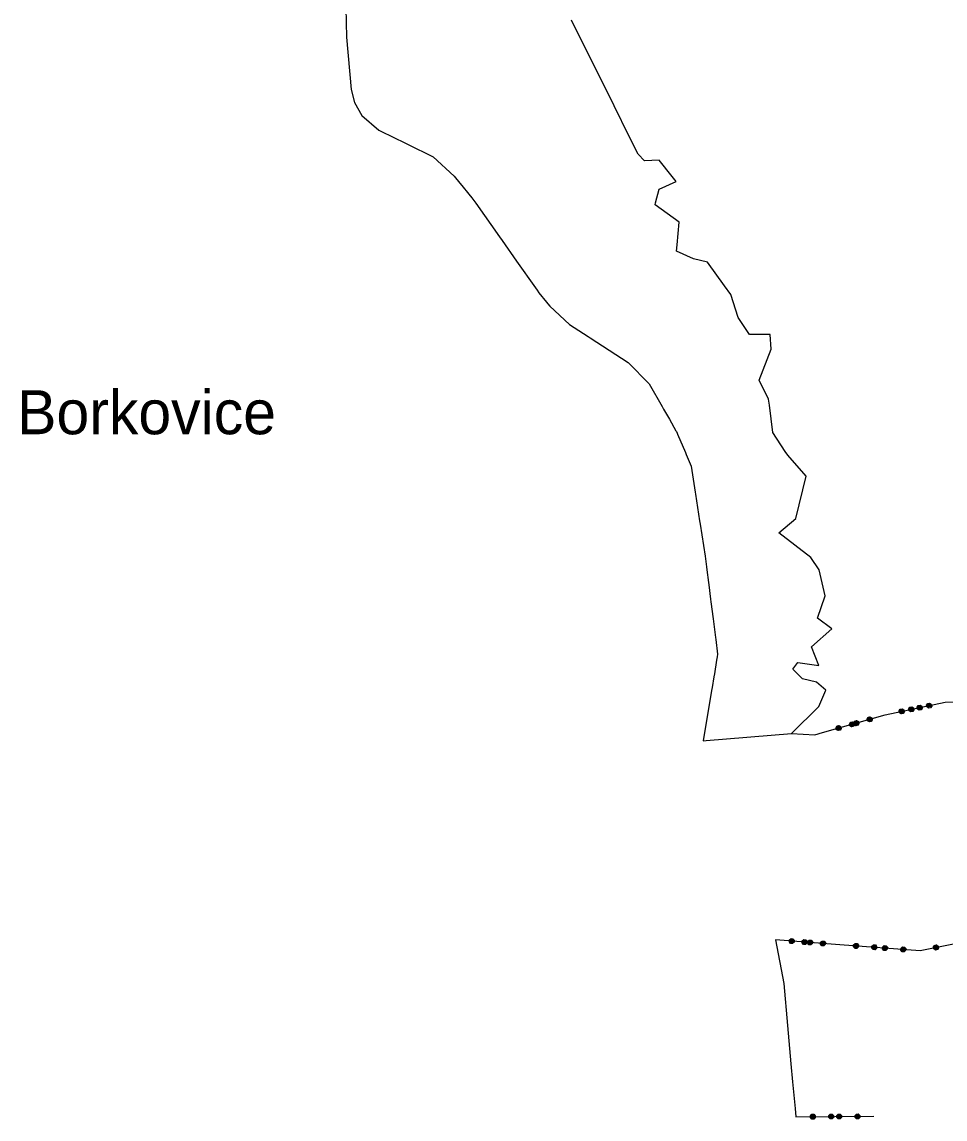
# Model space of a CAD drawing. Extents: x -738939 to -735528, y -1140462 to -1136895.
# Drawn here: x -738939 to -738311, y -1140462 to -1139715 of the extents above; entities that cross this region are included whole.
import ezdxf

# ---------------------------------------------------------------- set-up
doc = ezdxf.new("R2010")
doc.units = 0
for name, color, linetype in [('HRA_KU', 7, 'Continuous'), ('KU_OST', 7, 'Continuous'), ('OVNE_PRE', 7, 'Continuous')]:
    doc.layers.add(name, color=color, linetype=linetype)

msp = doc.modelspace()

# ---------------------------------------------------------------- linework, layer by layer
at = {"layer": 'HRA_KU'}
for points in [[(-738414.99, -1140199.58), (-738399.12, -1140200.49), (-738393.99, -1140199.05), (-738351.21, -1140187.04), (-738310.54, -1140178.29), (-738300.41, -1140178)], [(-738327.45, -1140180.29), (-738326.32, -1140181.02), (-738326.04, -1140182.34), (-738326.76, -1140183.47), (-738328.08, -1140183.75), (-738329.21, -1140183.02), (-738329.5, -1140181.7), (-738328.77, -1140180.57), (-738327.45, -1140180.29), (-738327.55, -1140180.52), (-738328.73, -1140180.77), (-738329.03, -1140181.25), (-738327.08, -1140180.82), (-738326.6, -1140181.13), (-738329.34, -1140181.72), (-738329.26, -1140182.11), (-738326.52, -1140181.52), (-738326.43, -1140181.91), (-738329.17, -1140182.5), (-738329.09, -1140182.89), (-738326.35, -1140182.3), (-738326.66, -1140182.78), (-738328.61, -1140183.2), (-738328.14, -1140183.51), (-738326.96, -1140183.25)], [(-738321, -1140178.9), (-738319.87, -1140179.63), (-738319.58, -1140180.95), (-738320.31, -1140182.08), (-738321.63, -1140182.36), (-738322.76, -1140181.63), (-738323.04, -1140180.31), (-738322.32, -1140179.19), (-738321, -1140178.9), (-738321.1, -1140179.13), (-738322.27, -1140179.38), (-738322.58, -1140179.86), (-738320.62, -1140179.44), (-738320.15, -1140179.74), (-738322.89, -1140180.33), (-738322.8, -1140180.72), (-738320.07, -1140180.13), (-738319.98, -1140180.53), (-738322.72, -1140181.11), (-738322.63, -1140181.51), (-738319.9, -1140180.92), (-738320.2, -1140181.39), (-738322.16, -1140181.81), (-738321.68, -1140182.12), (-738320.51, -1140181.87)], [(-738339.67, -1140182.92), (-738338.54, -1140183.65), (-738338.26, -1140184.97), (-738338.98, -1140186.1), (-738340.3, -1140186.38), (-738341.43, -1140185.65), (-738341.72, -1140184.33), (-738340.99, -1140183.2), (-738339.67, -1140182.92), (-738339.68, -1140183.13), (-738340.85, -1140183.38), (-738341.16, -1140183.85), (-738339.2, -1140183.43), (-738338.72, -1140183.74), (-738341.46, -1140184.33), (-738341.38, -1140184.72), (-738338.64, -1140184.13), (-738338.56, -1140184.52), (-738341.29, -1140185.11), (-738341.21, -1140185.5), (-738338.47, -1140184.91), (-738338.78, -1140185.39), (-738340.73, -1140185.81), (-738340.26, -1140186.12), (-738339.09, -1140185.86)], [(-738333.22, -1140181.53), (-738332.09, -1140182.26), (-738331.8, -1140183.58), (-738332.53, -1140184.71), (-738333.85, -1140184.99), (-738334.98, -1140184.26), (-738335.26, -1140182.95), (-738334.54, -1140181.82), (-738333.22, -1140181.53), (-738333.22, -1140181.74), (-738334.4, -1140181.99), (-738334.7, -1140182.47), (-738332.75, -1140182.05), (-738332.27, -1140182.35), (-738335.01, -1140182.94), (-738334.92, -1140183.33), (-738332.19, -1140182.74), (-738332.1, -1140183.13), (-738334.84, -1140183.72), (-738334.76, -1140184.11), (-738332.02, -1140183.53), (-738332.33, -1140184), (-738334.28, -1140184.42), (-738333.81, -1140184.73), (-738332.63, -1140184.48)], [(-738382.72, -1140194.23), (-738381.55, -1140194.88), (-738381.19, -1140196.18), (-738381.85, -1140197.36), (-738383.14, -1140197.72), (-738384.32, -1140197.06), (-738384.68, -1140195.76), (-738384.02, -1140194.59), (-738382.72, -1140194.23), (-738382.72, -1140194.43), (-738383.87, -1140194.76), (-738384.15, -1140195.25), (-738382.23, -1140194.71), (-738381.73, -1140194.99), (-738384.43, -1140195.74), (-738384.32, -1140196.13), (-738381.62, -1140195.37), (-738381.52, -1140195.76), (-738384.21, -1140196.51), (-738384.1, -1140196.9), (-738381.41, -1140196.14), (-738381.68, -1140196.64), (-738383.61, -1140197.18), (-738383.12, -1140197.45), (-738381.96, -1140197.13)], [(-738373.64, -1140191.68), (-738372.47, -1140192.33), (-738372.11, -1140193.63), (-738372.76, -1140194.81), (-738374.06, -1140195.17), (-738375.23, -1140194.51), (-738375.6, -1140193.21), (-738374.94, -1140192.04), (-738373.64, -1140191.68), (-738373.64, -1140191.88), (-738374.79, -1140192.21), (-738375.07, -1140192.7), (-738373.14, -1140192.16), (-738372.65, -1140192.44), (-738375.34, -1140193.19), (-738375.24, -1140193.58), (-738372.54, -1140192.82), (-738372.43, -1140193.21), (-738375.13, -1140193.96), (-738375.02, -1140194.35), (-738372.32, -1140193.59), (-738372.6, -1140194.09), (-738374.53, -1140194.63), (-738374.03, -1140194.9), (-738372.88, -1140194.58)], [(-738370.69, -1140190.84), (-738369.52, -1140191.5), (-738369.15, -1140192.8), (-738369.81, -1140193.97), (-738371.11, -1140194.34), (-738372.28, -1140193.68), (-738372.65, -1140192.38), (-738371.99, -1140191.21), (-738370.69, -1140190.84), (-738370.78, -1140191.08), (-738371.94, -1140191.4), (-738372.21, -1140191.9), (-738370.29, -1140191.35), (-738369.79, -1140191.63), (-738372.49, -1140192.39), (-738372.38, -1140192.77), (-738369.69, -1140192.02), (-738369.58, -1140192.4), (-738372.27, -1140193.16), (-738372.17, -1140193.54), (-738369.47, -1140192.79), (-738369.75, -1140193.28), (-738371.67, -1140193.82), (-738371.18, -1140194.1), (-738370.02, -1140193.77)], [(-738361.61, -1140188.3), (-738360.44, -1140188.95), (-738360.07, -1140190.25), (-738360.73, -1140191.42), (-738362.03, -1140191.79), (-738363.2, -1140191.13), (-738363.57, -1140189.83), (-738362.91, -1140188.66), (-738361.61, -1140188.3), (-738361.7, -1140188.53), (-738362.85, -1140188.85), (-738363.13, -1140189.35), (-738361.21, -1140188.81), (-738360.71, -1140189.08), (-738363.41, -1140189.84), (-738363.3, -1140190.22), (-738360.6, -1140189.47), (-738360.5, -1140189.85), (-738363.19, -1140190.61), (-738363.08, -1140190.99), (-738360.39, -1140190.24), (-738360.66, -1140190.73), (-738362.59, -1140191.27), (-738362.1, -1140191.55), (-738360.94, -1140191.22)], [(-738241.47, -1140330.32), (-738327.46, -1140347.5), (-738382.19, -1140343.52), (-738425.77, -1140340.11), (-738420.11, -1140369.81), (-738417.67, -1140398.44), (-738415.46, -1140424.43), (-738414.4, -1140436.82), (-738412.51, -1140455.01), (-738411.93, -1140460.53), (-738359.03, -1140460.24)], [(-738415.58, -1140342.52), (-738416.45, -1140341.5), (-738416.34, -1140340.15), (-738415.32, -1140339.28), (-738413.98, -1140339.38), (-738413.1, -1140340.4), (-738413.21, -1140341.75), (-738414.23, -1140342.62), (-738415.58, -1140342.52), (-738415.41, -1140342.33), (-738414.21, -1140342.42), (-738413.78, -1140342.05), (-738415.78, -1140341.9), (-738416.15, -1140341.47), (-738413.35, -1140341.69), (-738413.32, -1140341.29), (-738416.12, -1140341.07), (-738416.08, -1140340.67), (-738413.29, -1140340.89), (-738413.26, -1140340.49), (-738416.05, -1140340.27), (-738415.62, -1140339.9), (-738413.63, -1140340.06), (-738414, -1140339.63), (-738415.19, -1140339.54)], [(-738406.89, -1140343.2), (-738407.76, -1140342.18), (-738407.66, -1140340.83), (-738406.64, -1140339.96), (-738405.29, -1140340.06), (-738404.42, -1140341.08), (-738404.52, -1140342.43), (-738405.54, -1140343.3), (-738406.89, -1140343.2), (-738406.72, -1140343.01), (-738405.53, -1140343.1), (-738405.1, -1140342.73), (-738407.09, -1140342.58), (-738407.46, -1140342.15), (-738404.67, -1140342.37), (-738404.64, -1140341.97), (-738407.43, -1140341.75), (-738407.4, -1140341.35), (-738404.61, -1140341.57), (-738404.58, -1140341.17), (-738407.37, -1140340.95), (-738406.94, -1140340.58), (-738404.94, -1140340.74), (-738405.31, -1140340.31), (-738406.51, -1140340.22)], [(-738403.11, -1140343.49), (-738403.99, -1140342.46), (-738403.88, -1140341.12), (-738402.86, -1140340.24), (-738401.52, -1140340.35), (-738400.64, -1140341.37), (-738400.75, -1140342.72), (-738401.77, -1140343.59), (-738403.11, -1140343.49), (-738403.05, -1140343.29), (-738401.85, -1140343.38), (-738401.42, -1140343.01), (-738403.42, -1140342.86), (-738403.78, -1140342.43), (-738400.99, -1140342.65), (-738400.96, -1140342.25), (-738403.75, -1140342.03), (-738403.72, -1140341.63), (-738400.93, -1140341.85), (-738400.9, -1140341.45), (-738403.69, -1140341.23), (-738403.26, -1140340.87), (-738401.27, -1140341.02), (-738401.63, -1140340.59), (-738402.83, -1140340.5)], [(-738394.43, -1140344.16), (-738395.3, -1140343.14), (-738395.2, -1140341.8), (-738394.17, -1140340.92), (-738392.83, -1140341.03), (-738391.96, -1140342.05), (-738392.06, -1140343.4), (-738393.08, -1140344.27), (-738394.43, -1140344.16), (-738394.36, -1140343.97), (-738393.17, -1140344.06), (-738392.74, -1140343.69), (-738394.73, -1140343.54), (-738395.1, -1140343.11), (-738392.31, -1140343.33), (-738392.27, -1140342.93), (-738395.07, -1140342.71), (-738395.04, -1140342.31), (-738392.24, -1140342.53), (-738392.21, -1140342.13), (-738395, -1140341.91), (-738394.57, -1140341.55), (-738392.58, -1140341.7), (-738392.95, -1140341.27), (-738394.14, -1140341.18)], [(-738371.98, -1140345.87), (-738372.86, -1140344.85), (-738372.76, -1140343.5), (-738371.75, -1140342.63), (-738370.4, -1140342.72), (-738369.52, -1140343.74), (-738369.62, -1140345.09), (-738370.64, -1140345.96), (-738371.98, -1140345.87), (-738371.82, -1140345.68), (-738370.62, -1140345.76), (-738370.19, -1140345.39), (-738372.19, -1140345.25), (-738372.56, -1140344.82), (-738369.77, -1140345.03), (-738369.74, -1140344.63), (-738372.53, -1140344.42), (-738372.5, -1140344.02), (-738369.71, -1140344.23), (-738369.68, -1140343.83), (-738372.47, -1140343.63), (-738372.04, -1140343.26), (-738370.05, -1140343.4), (-738370.42, -1140342.97), (-738371.62, -1140342.89)], [(-738359.52, -1140346.77), (-738360.39, -1140345.76), (-738360.3, -1140344.41), (-738359.28, -1140343.53), (-738357.93, -1140343.63), (-738357.06, -1140344.65), (-738357.15, -1140345.99), (-738358.17, -1140346.87), (-738359.52, -1140346.77), (-738359.45, -1140346.58), (-738358.26, -1140346.66), (-738357.83, -1140346.29), (-738359.82, -1140346.15), (-738360.19, -1140345.72), (-738357.4, -1140345.92), (-738357.37, -1140345.53), (-738360.16, -1140345.32), (-738360.13, -1140344.92), (-738357.34, -1140345.13), (-738357.31, -1140344.73), (-738360.1, -1140344.52), (-738359.68, -1140344.15), (-738357.68, -1140344.3), (-738358.05, -1140343.87), (-738359.25, -1140343.78)], [(-738352.16, -1140347.31), (-738353.04, -1140346.29), (-738352.94, -1140344.95), (-738351.93, -1140344.07), (-738350.58, -1140344.16), (-738349.7, -1140345.18), (-738349.8, -1140346.53), (-738350.81, -1140347.41), (-738352.16, -1140347.31), (-738352, -1140347.12), (-738350.8, -1140347.21), (-738350.37, -1140346.84), (-738352.37, -1140346.69), (-738352.74, -1140346.26), (-738349.94, -1140346.47), (-738349.92, -1140346.07), (-738352.71, -1140345.86), (-738352.68, -1140345.47), (-738349.89, -1140345.67), (-738349.86, -1140345.27), (-738352.65, -1140345.07), (-738352.22, -1140344.7), (-738350.23, -1140344.84), (-738350.6, -1140344.41), (-738351.79, -1140344.33)], [(-738339.69, -1140348.21), (-738340.57, -1140347.2), (-738340.47, -1140345.85), (-738339.46, -1140344.97), (-738338.11, -1140345.07), (-738337.23, -1140346.09), (-738337.33, -1140347.43), (-738338.35, -1140348.31), (-738339.69, -1140348.21), (-738339.63, -1140348.02), (-738338.43, -1140348.11), (-738338, -1140347.74), (-738340, -1140347.59), (-738340.37, -1140347.16), (-738337.58, -1140347.37), (-738337.55, -1140346.97), (-738340.34, -1140346.76), (-738340.31, -1140346.36), (-738337.52, -1140346.57), (-738337.49, -1140346.17), (-738340.28, -1140345.97), (-738339.85, -1140345.6), (-738337.86, -1140345.74), (-738338.23, -1140345.31), (-738339.43, -1140345.23)], [(-738317, -1140347.04), (-738318.11, -1140346.3), (-738318.38, -1140344.97), (-738317.63, -1140343.86), (-738316.31, -1140343.59), (-738315.19, -1140344.34), (-738314.93, -1140345.66), (-738315.67, -1140346.78), (-738317, -1140347.04), (-738316.89, -1140346.82), (-738315.71, -1140346.58), (-738315.4, -1140346.11), (-738317.36, -1140346.5), (-738317.83, -1140346.19), (-738315.08, -1140345.64), (-738315.16, -1140345.25), (-738317.91, -1140345.8), (-738317.99, -1140345.41), (-738315.24, -1140344.86), (-738315.32, -1140344.46), (-738318.07, -1140345.01), (-738317.75, -1140344.54), (-738315.79, -1140344.15), (-738316.26, -1140343.84), (-738317.44, -1140344.07)], [(-738399.79, -1140458.86), (-738398.83, -1140459.81), (-738398.83, -1140461.16), (-738399.77, -1140462.11), (-738401.12, -1140462.12), (-738402.08, -1140461.17), (-738402.08, -1140459.82), (-738401.14, -1140458.87), (-738399.79, -1140458.86), (-738399.84, -1140459.06), (-738401.04, -1140459.07), (-738401.44, -1140459.47), (-738399.44, -1140459.46), (-738399.03, -1140459.86), (-738401.83, -1140459.87), (-738401.83, -1140460.27), (-738399.03, -1140460.26), (-738399.03, -1140460.66), (-738401.83, -1140460.67), (-738401.83, -1140461.07), (-738399.03, -1140461.06), (-738399.43, -1140461.46), (-738401.43, -1140461.47), (-738401.02, -1140461.87), (-738399.82, -1140461.86)], [(-738387.29, -1140458.8), (-738386.33, -1140459.74), (-738386.33, -1140461.09), (-738387.27, -1140462.05), (-738388.62, -1140462.06), (-738389.58, -1140461.11), (-738389.58, -1140459.76), (-738388.64, -1140458.81), (-738387.29, -1140458.8), (-738387.44, -1140459), (-738388.64, -1140459.01), (-738389.04, -1140459.41), (-738387.04, -1140459.4), (-738386.63, -1140459.8), (-738389.43, -1140459.81), (-738389.43, -1140460.21), (-738386.63, -1140460.2), (-738386.63, -1140460.6), (-738389.43, -1140460.61), (-738389.43, -1140461.01), (-738386.63, -1140461), (-738387.03, -1140461.4), (-738389.03, -1140461.41), (-738388.62, -1140461.81), (-738387.42, -1140461.8)], [(-738381.89, -1140458.76), (-738380.93, -1140459.71), (-738380.93, -1140461.06), (-738381.87, -1140462.01), (-738383.22, -1140462.02), (-738384.18, -1140461.07), (-738384.18, -1140459.72), (-738383.24, -1140458.77), (-738381.89, -1140458.76), (-738381.94, -1140458.96), (-738383.14, -1140458.97), (-738383.53, -1140459.37), (-738381.53, -1140459.36), (-738381.13, -1140459.76), (-738383.93, -1140459.77), (-738383.93, -1140460.17), (-738381.13, -1140460.16), (-738381.13, -1140460.56), (-738383.93, -1140460.57), (-738383.93, -1140460.97), (-738381.13, -1140460.96), (-738381.52, -1140461.36), (-738383.52, -1140461.37), (-738383.12, -1140461.77), (-738381.92, -1140461.76)], [(-738369.39, -1140458.7), (-738368.43, -1140459.65), (-738368.43, -1140461), (-738369.37, -1140461.95), (-738370.72, -1140461.96), (-738371.68, -1140461.01), (-738371.68, -1140459.66), (-738370.74, -1140458.71), (-738369.39, -1140458.7), (-738369.54, -1140458.9), (-738370.74, -1140458.91), (-738371.13, -1140459.31), (-738369.13, -1140459.3), (-738368.73, -1140459.7), (-738371.53, -1140459.71), (-738371.53, -1140460.11), (-738368.73, -1140460.1), (-738368.73, -1140460.5), (-738371.53, -1140460.51), (-738371.53, -1140460.91), (-738368.73, -1140460.9), (-738369.12, -1140461.3), (-738371.12, -1140461.31), (-738370.72, -1140461.71), (-738369.52, -1140461.7)]]:
    msp.add_lwpolyline(points, dxfattribs=at)
at = {"layer": 'OVNE_PRE'}
for points in [[(-738718.68, -1139685.49), (-738717.7, -1139725.72), (-738714.67, -1139761.22), (-738712.33, -1139770.2), (-738707.3, -1139779), (-738695.69, -1139788.97), (-738694.49, -1139789.56), (-738677.57, -1139797.91), (-738676.3, -1139798.54), (-738658.78, -1139807.18), (-738644.43, -1139820.28), (-738640.58, -1139825.07), (-738639.32, -1139826.63), (-738634.51, -1139832.62), (-738632.57, -1139835.04), (-738629.69, -1139838.63), (-738613.57, -1139861.61), (-738611.78, -1139864.16), (-738602.05, -1139878.03), (-738589.26, -1139896.25), (-738588.11, -1139897.88), (-738586.85, -1139899.69), (-738581.77, -1139905.96), (-738580.83, -1139907.12), (-738579.49, -1139908.77), (-738565.96, -1139921.35), (-738553.44, -1139929.46), (-738552.07, -1139930.35), (-738526.16, -1139947.15), (-738511.89, -1139961.53), (-738503.03, -1139977.11), (-738502.03, -1139978.87), (-738500.06, -1139982.34), (-738498.1, -1139985.78), (-738493.6, -1139993.69), (-738493.32, -1139994.18), (-738492.84, -1139995.28), (-738492.6, -1139995.85), (-738487.18, -1140008.36), (-738486.61, -1140009.68), (-738483.18, -1140017.61), (-738480.49, -1140035.29), (-738480.26, -1140036.79), (-738477.5, -1140054.92), (-738477.17, -1140057.07), (-738473.83, -1140079.01), (-738473.14, -1140084.34), (-738472.91, -1140086.13), (-738472.63, -1140088.33), (-738471.53, -1140096.88), (-738471.32, -1140098.53), (-738470.08, -1140108.15), (-738469.83, -1140110.13), (-738468.34, -1140121.68), (-738468.12, -1140123.39), (-738466.71, -1140134.37), (-738466.53, -1140135.77), (-738465.27, -1140145.58), (-738465.6, -1140147.56), (-738465.94, -1140149.65), (-738467.48, -1140159.02), (-738467.8, -1140160.97), (-738469.03, -1140168.35), (-738469.38, -1140170.48), (-738474.98, -1140204.56), (-738473.11, -1140204.4), (-738414.99, -1140199.58)], [(-738414.99, -1140199.58), (-738396.34, -1140181.3), (-738391.71, -1140170.21), (-738398.08, -1140164.8), (-738407.47, -1140162.48), (-738413.99, -1140155.79), (-738410.63, -1140151.35), (-738396.4, -1140153.36), (-738401.34, -1140140.62), (-738387.57, -1140128.34), (-738397.37, -1140121.14), (-738392.14, -1140105.89), (-738396.19, -1140088.24), (-738401.78, -1140079.95), (-738423.61, -1140062.97), (-738412.12, -1140053.36), (-738404.97, -1140024.39), (-738417.59, -1140010.21), (-738419.28, -1140007.62), (-738427.7, -1139994.76), (-738430.04, -1139976.08), (-738430.53, -1139972.13), (-738437.02, -1139959.15), (-738428.92, -1139938.08), (-738429.4, -1139928.01), (-738443.61, -1139928.11), (-738451.25, -1139916.47), (-738456.25, -1139900.74), (-738460.55, -1139894.89), (-738472.21, -1139878.83), (-738481.65, -1139876.47), (-738493.19, -1139871.32), (-738492.81, -1139866.9), (-738491.43, -1139851.64), (-738507.84, -1139839.69), (-738507.6, -1139838.48), (-738504.95, -1139829.04), (-738493.42, -1139823.91), (-738496.11, -1139820.53), (-738504.97, -1139809.47), (-738515.08, -1139809.83), (-738519.29, -1139805.39), (-738525.36, -1139793.17), (-738535.7, -1139772.36), (-738550.88, -1139741.79), (-738555.97, -1139731.53), (-738564.64, -1139714.01)]]:
    msp.add_lwpolyline(points, dxfattribs=at)

# ---------------------------------------------------------------- texts
at = {"layer": 'KU_OST'}
msp.add_text('Borkovice', height=30, dxfattribs=at).set_placement((-738941.85, -1139995.95))

doc.saveas('drawing.dxf')
